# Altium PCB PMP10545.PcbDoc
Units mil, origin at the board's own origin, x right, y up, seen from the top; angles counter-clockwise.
Board outline 3000 x 2500 mil, 2 copper layers (Top Layer, Bottom Layer), stack 62 mil thick; 63 components, 23 nets, 122 pads, 5 vias.
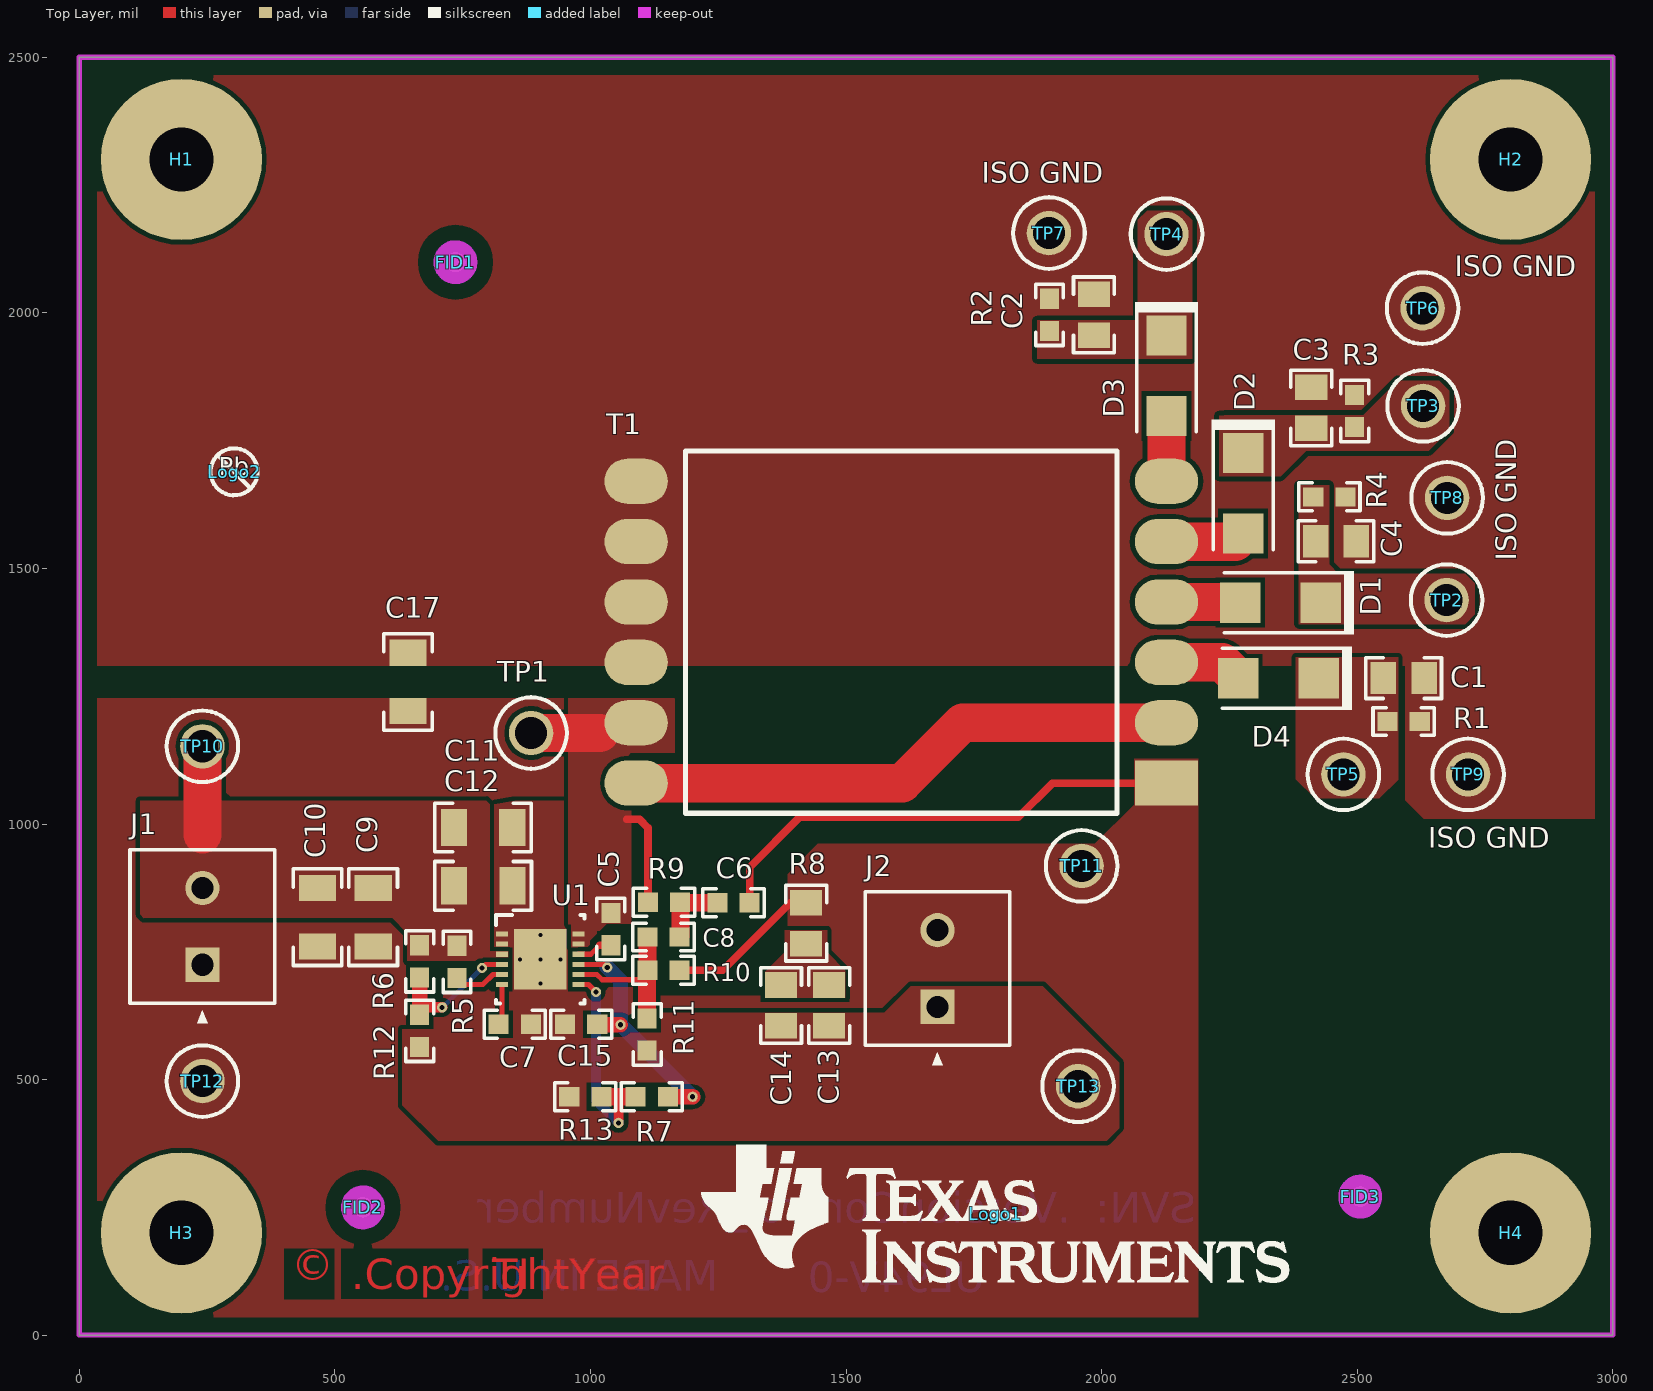
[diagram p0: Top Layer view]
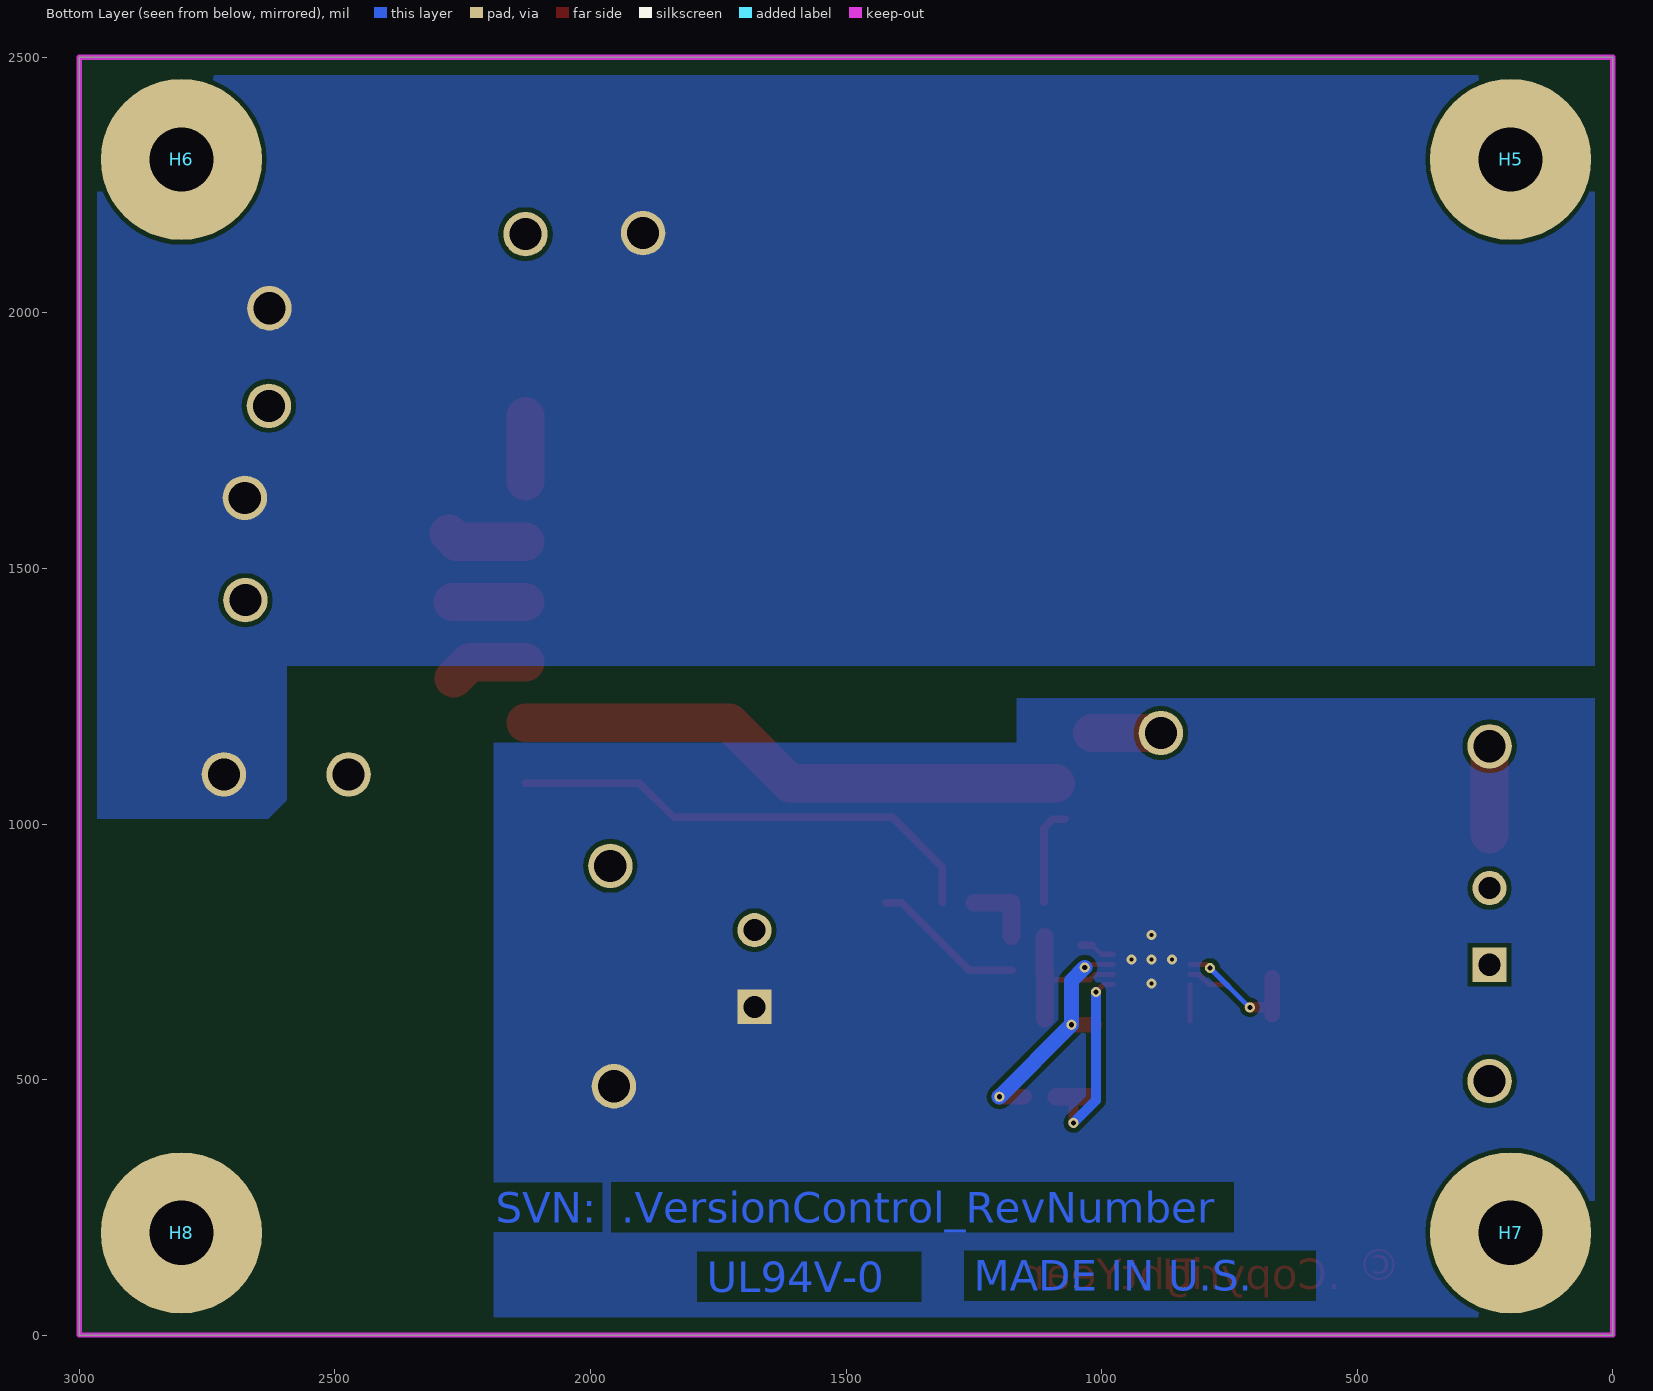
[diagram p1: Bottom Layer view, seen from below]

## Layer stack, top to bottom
Top Solder: solder mask 0.4, Solder Resist, Dk 3.5
Top Layer: signal copper 1.4
Dielectric1: core 59.2, FR-4, Dk 4.8
Bottom Layer: signal copper 1.4
Bottom Solder: solder mask 0.4, Solder Resist, Dk 3.5

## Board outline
0,0 3000,0 3000,2500 0,2500

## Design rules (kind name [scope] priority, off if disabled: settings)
AcuteAngle [All] p1: minimum=4.50000000000000E+0001 checktracksonly=FALSE
AssemblyTestPointUsage [All] p1: valid=2
Clearance Clearance_BoardEdge_MountingHoles [OnCopper and InComponentClass('Mounting Holes') vs IsKeepOut] p1: gap=30
Clearance Clearance_BoardEdge_Poly [OnCopper and InPoly vs IsKeepOut] p2: gap=30
Clearance Clearance_BoardEdge [OnCopper and Not InComponentClass('Logo') and not InComponentClass('FiducialMark') and not InRegion(1000,500,4000,800) and Not IsKeepout vs IsKeepOut] p3: gap=30
Clearance Clearance_Poly [InPolygon] p4: gap=9
Clearance [All] p5: gap=9
ComponentClearance ComponentClearance_Shunt [InComponentClass('Header') vs InComponentClass('Shunt')] p1: gap=0 collisioncheckmode=3 verticalgap=0 showdistances=FALSE
ComponentClearance ComponentClearance_MountingHoles_FiducialMarks [InComponentClass('Mounting Holes') vs InComponentClass('FiducialMark')] p2: gap=50 collisioncheckmode=3 verticalgap=10 showdistances=FALSE
ComponentClearance ComponentClearance_Logo [InComponentClass('Logo')] p3: gap=50 collisioncheckmode=3 verticalgap=10 showdistances=FALSE
ComponentClearance ComponentClearance_ScrewToNut [(HasFootprint('NY PMS 440 0025 PH')) vs (HasFootprint('Keystone_1902C'))] p4: gap=5 collisioncheckmode=3 verticalgap=10 showdistances=FALSE
ComponentClearance ComponentClearance_MountingHoles [InComponentClass('Mounting Holes')] p5: gap=50 collisioncheckmode=3 verticalgap=100000 showdistances=FALSE
ComponentClearance ComponentClearance_SmallPassives [HasFootprint('0201*') or HasFootprint('0402*') or HasFootprint('0508') or HasFootprint('0603*') or HasFootprint('0612') or HasFootprint('0805*') or HasFootprint('0815*') or HasFootprint('0830*') or HasFootprint('1206*') or HasFootprint('1210*') or HasFootprint('1808*') or HasFootprint('1812*') or HasFootprint('1825*') or HasFootprint('2010*') or HasFootprint('2220*') or HasFootprint('2225*') or HasFootprint('2512*') or HasFootprint('2728*') or HasFootprint('3518*') vs HasFootprint('0201*') or HasFootprint('0402*') or HasFootprint('0508') or HasFootprint('0603*') or HasFootprint('0612') or HasFootprint('0805*') or HasFootprint('0815*') or HasFootprint('0830*') or HasFootprint('1206*') or HasFootprint('1210*') or HasFootprint('1808*') or HasFootprint('1812*') or HasFootprint('1825*') or HasFootprint('2010*') or HasFootprint('2220*') or HasFootprint('2225*') or HasFootprint('2512*') or HasFootprint('2728*') or HasFootprint('3518*')] p6: gap=20 collisioncheckmode=3 verticalgap=10 showdistances=FALSE
ComponentClearance ComponentClearance_THtoSMT [IsThruComponent vs IsSMTComponent] p7: gap=35 collisioncheckmode=3 verticalgap=30 showdistances=FALSE
ComponentClearance ComponentClearance_THtoTH [IsThruComponent vs IsThruComponent] p8: gap=50 collisioncheckmode=3 verticalgap=30 showdistances=FALSE
ComponentClearance [All] p9: gap=20 collisioncheckmode=3 verticalgap=10 showdistances=FALSE
DiffPairsRouting [All] p1: maxlimit=100 minlimit=10 mostfreqgap=10 toplayer_minwidth=15 toplayer_maxwidth=15 toplayer_prefwidth=15 bottomlayer_minwidth=15 bottomlayer_maxwidth=15 bottomlayer_prefwidth=15 maxuncoupledlength=1000
FabricationTestPointUsage TestPointUsage [All] p1: valid=2 allowmultiple=FALSE
FabricationTestpoint Testpoint [All] p1: side=3 testpointundercomponent=TRUE minsize=40 maxsize=100 preferedsize=60 minholesize=0 maxholesize=40 preferedholesize=32 testpointgrid=1 allowsidetop=TRUE allowsidebottom=TRUE usegrid=TRUE gridtolerance=0.01
FanoutControl Fanout_LCC [IsLCC] p1: bgadir=Out bgaviamode=Centered fanoutstyle=Auto fanoutdirection=Alternating viagrid=1 // Fanout_LCC (Default Rule)
FanoutControl Fanout_BGA [IsBGA] p2: bgadir=Out bgaviamode=Centered fanoutstyle=Auto fanoutdirection=Alternating viagrid=1 // Fanout_BGA (Default Rule)
FanoutControl Fanout_Default [All] p4: bgadir=Out bgaviamode=Centered fanoutstyle=Auto fanoutdirection=Alternating viagrid=1 // Fanout_Default (Default Rule)
FanoutControl Fanout_Small [(CompPinCount < 5)] p5: bgadir=Out bgaviamode=Centered fanoutstyle=Auto fanoutdirection=OutThenIn viagrid=1 // Fanout_Small (Default Rule)
HoleSize [All] p1: absolutevalues=TRUE maxlimit=251 minlimit=8 maxpercent=80.000 minpercent=20.000
MinimumAnnularRing MinimumAnnularRing_ThermalPadVias [IsVia and InAnyComponent] p1: minimumring=5
MinimumAnnularRing [All] p2: minimumring=5
MinimumSolderMaskSliver MinimumSolderMaskSliver_Logo [InComponentClass('Logo') vs InComponentClass('Logo')] p1: minsoldermaskwidth=0.7
MinimumSolderMaskSliver [All] p2: minsoldermaskwidth=3.94
PlaneConnect [All] p1: planeconnectstyle=Direct reliefexpansion=10 reliefentries=4 reliefconductorwidth=10 reliefairgap=10
PolygonConnect [All] p1: connectstyle=Direct reliefconductorwidth=10 reliefentries=4 polygonreliefangle="90 Angle" airgapwidth=10
RoutingVias ThermalPadVias [IsVia and InAnyComponent] p1: holewidth=7.87 width=19.68 viastyle="Through Hole" minholewidth=10 minwidth=20 maxholewidth=12.99 maxwidth=23.62
RoutingVias [All] p2: holewidth=16 width=34 viastyle="Through Hole" minholewidth=10 minwidth=20 maxholewidth=40 maxwidth=65
SMDToCorner [All] p1: distance=30000
SilkToSilkClearance SilkToSilkClearance_Pb-FreeLogo [(HasFootprint('Pb-Free_Overlay_Medium') OR HasFootprint('Pb-Free_Overlay_Small')) vs (HasFootprint('Pb-Free_Overlay_Medium') OR HasFootprint('Pb-Free_Overlay_Small'))] p1: silktosilkclearance=0
SilkToSilkClearance [All] p2: silktosilkclearance=5
SilkToSolderMaskClearance SilkscreenOverComponentPads [IsPad] p1: minsilkscreentomaskgap=5 clearancetoexposedcopper=TRUE
SolderMaskExpansion [All] p1: expansion=1.97
UnpouredPolygon [All] p1: allowunpoured=FALSE
Width [All] p1: maxlimit=100 minlimit=6 preferedwidth=10 checkconnectedcopper=TRUE
15 further rules are at their usual default settings.

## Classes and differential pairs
component class "Mounting Holes": H1 H2 H3 H4
component class Logo: Logo1
component class PMP10545_Hardware_ANSI-B: FID1 FID2 FID3 H1 H2 H3 H4 H5 H6 H7 H8 Logo1 Logo2
component class FiducialMark: FID1 FID2 FID3
component class "PMP10545 Schematic rev 4SchDoc": C1 C2 C3 C4 C5 C6 C7 C8 C9 C10 C11 C12 C13 C14 C15 C17 D1 D2 D3 D4 J1 J2 R1 R2 R3 R4 R5 R6 R7 R8 R9 R10 R11 R12 R13 T1 TP1 TP2 TP3 TP4 TP5 TP6 TP7 TP8 TP9 TP10 TP11 TP12 TP13 U1

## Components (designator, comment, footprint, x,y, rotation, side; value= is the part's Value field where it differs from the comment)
C1 "EMK212BJ106KG-T" 0805_HV 2591,1285.52 r0 top
C2 "EMK212BJ106KG-T" 0805_HV 1985,1996 r90 top
C3 "EMK212BJ106KG-T" 0805_HV 2410,1814 r90 top
C4 "EMK212BJ106KG-T" 0805_HV 2458.55,1553 r0 top
C5 "C0603C104J3RAC" 0603 1039.99,794.35 r270 top
C6 "C0603C222K5RAC" 0603 1280,846 r0 top
C7 "GRM188R71C223KA01D" 0603 851.99,608.35 r0 top
C8 "C0603C104J3RAC" 0603 1143,779 r180 top
C9 "GRM31CR61H225KA88L" 1206 574.99,817.67 r270 top
C10 "GRM31CR61H225KA88L" 1206 465.99,817.67 r270 top
C11 "GRM31CR61H225KA88L" 1206 789.99,993.04 r0 top
C12 "GRM31CR61H225KA88L" 1206 790.3,879.04 r0 top
C13 "EMK212BJ106KG-T" 0805_HV 1466.99,645.04 r270 top
C14 "EMK212BJ106KG-T" 0805_HV 1372.99,645.04 r270 top
C15 "GRM188R71E105KA12D" 0603 981.99,608.35 r180 top
C17 "VJ1206A102JXGAT5Z" 1206 643,1278 r270 top
D1 "ES1A-13-F" SMA 2350,1433 r180 top
D2 "ES1A-13-F" SMA 2277,1647 r270 top
D3 "ES1A-13-F" SMA 2127,1877 r270 top
D4 "ES1A-13-F" SMA 2346,1285 r180 top
FID1 "Fiducial" Fiducial10-20 736,2099 r0 top
FID2 "Fiducial" Fiducial10-20 555,250 r0 top
FID3 "Fiducial" Fiducial10-20 2506,271 r0 top
H1 "NY PMS 440 0025 PH" "NY PMS 440 0025 PH" 200,2300 r0 top locked
H2 "NY PMS 440 0025 PH" "NY PMS 440 0025 PH" 2800,2300 r0 top locked
H3 "NY PMS 440 0025 PH" "NY PMS 440 0025 PH" 200,200 r0 top locked
H4 "NY PMS 440 0025 PH" "NY PMS 440 0025 PH" 2800,200 r0 top locked
H5 "1902C" Keystone_1902C 200,2300 r180 bottom locked
H6 "1902C" Keystone_1902C 2800,2300 r180 bottom locked
H7 "1902C" Keystone_1902C 200,200 r180 bottom locked
H8 "1902C" Keystone_1902C 2800,200 r180 bottom locked
J1 "Vin" PhoenixConact_1727010 240.99,799.67 r90 top
J2 "Vout Primary" PhoenixConact_1727010 1678.99,717.35 r90 top
Logo1 "Texas Instruments" TI_Stacked_Overlay_Medium 1792,238 r0 top
Logo2 "Pb-Free Symbol" Pb-Free_Overlay_Small 303,1689 r0 top
R1 "CRCW06032K00FKEA" 0603 2591,1200.52 r180 top
R2 "CRCW06032K00FKEA" 0603 1898,1996 r270 top
R3 "CRCW06032K00FKEA" 0603 2495,1808 r270 top
R4 "CRCW06032K00FKEA" 0603 2445.55,1640 r180 top
R5 "CRCW0603487KFKEA" 0603 738.99,730.35 r90 top
R6 "RC0603FR-07127KL" 0603 665.99,731.35 r90 top
R7 "CRCW06030000Z0EA" 0603 1119.99,466.35 r180 top
R8 "ERJ-6RQFR47V" 0805_HV 1422,806 r90 top
R9 "CRCW0603100KFKEA" 0603 1144,847 r0 top
R10 "CRCW060310K0FKEA" 0603 1143,714 r0 top
R11 "CRCW06032K00FKEA" 0603 1110.99,588.35 r90 top
R12 "CRCW060318K2FKEA" 0603 665.99,595.35 r90 top
R13 "CRCW06030000Z0EA" 0603 989.99,466.35 r0 top
T1 "Coiltronics, VP5-0083" VP5 2127,1080 r180 top
TP1 "Vsw Pri" Keystone5014 884,1178 r0 top
TP2 "Vo1" Keystone5014 2675,1438 r0 top
TP3 "Vo2" Keystone5014 2629,1818 r0 top
TP4 "Vo3" Keystone5014 2127,2154 r0 top
TP5 "Vo4" Keystone5014 2473,1097 r0 top
TP6 "ISO GND" Keystone5011 2628,2009 r0 top
TP7 "ISO GND" Keystone5011 1897,2156 r0 top
TP8 "ISO GND" Keystone5011 2676,1638 r0 top
TP9 "ISO GND" Keystone5011 2717,1097 r0 top
TP10 "+Vin" Keystone5010 241,1152 r0 top
TP11 "GNDout" Keystone5011 1961,918 r0 top
TP12 "GNDin" Keystone5011 241,497 r0 top
TP13 "-Vout" Keystone5127 1954,487 r0 top
U1 "LM5160DNT" DNT0012B 901.99,735.35 r0 top

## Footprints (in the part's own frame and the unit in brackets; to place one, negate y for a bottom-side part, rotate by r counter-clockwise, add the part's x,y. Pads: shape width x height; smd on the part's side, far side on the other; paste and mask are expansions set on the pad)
0603 [mm] "0603 from SM-752 data"
  rect 1x0.95 smd: 1(-0.8,0) 2(0.8,0)
  silkscreen extent -1.52,-0.69 1.52,0.69, body extent -0.87,-0.47 0.87,0.47, height 0.85
0805_HV [mil] "0805 with 30mil clearance between pads"
  rect 50x63 smd: 1(-40,0) 2(40,0)
  silkscreen extent -74,-40 74,40, body extent -43,-29 43,29, height 43
1206 [mm] "1206 from SM-752 data"
  rect 1.3x1.85 smd: 1(-1.45,0) 2(1.45,0)
  silkscreen extent -2.4,-1.21 2.4,1.21, body extent -1.7,-0.9 1.7,0.9, height 1.35
DNT0012B [mm] "SON, 12-Leads, Body 4x4mm, Pitch 0.5mm"
  rect 0.6x0.25 smd: 1(-1.9,1.25) 2(-1.9,0.75) 3(-1.9,0.25) 4(-1.9,-0.25) 5(-1.9,-0.75) 6(-1.9,-1.25) 7(1.9,-1.25) 8(1.9,-0.75) 9(1.9,-0.25) 10(1.9,0.25) 11(1.9,0.75) 12(1.9,1.25)
  rect 2.6x3 smd paste-1.3: 13(0,0)
  silkscreen extent -2.2,-2.2 2.2,2.2, body extent -2.05,-2.05 2.05,2.05, height 0.81
Fiducial10-20 [mm]
  round 1 smd mask+0.5: 1(0,0)
  Top Layer keep-out circle w1.178: c0,0 r0.5
Keystone5010 [mil] "Keystone Multipurpose loops"
  round 87 hole 63: 1(0,0)
  silkscreen extent -70,-70 70,70, body extent -63,-63 63,62, height 319
Keystone5011 [mil] "Keystone Multipurpose loops"
  round 87 hole 63: 1(0,0)
  silkscreen extent -70,-70 70,70, body extent -63,-63 63,62, height 319
Keystone5014 [mil] "Keystone Multipurpose loops"
  round 87 hole 63: 1(0,0)
  silkscreen extent -70,-70 70,70, body extent -63,-63 63,62, height 319
Keystone5127 [mil] "Keystone Multipurpose loops"
  round 87 hole 63: 1(0,0)
  silkscreen extent -70,-70 70,70, body extent -63,-63 63,62, height 319
Keystone_1902C [mil] "Hex Standoff, 4-40 threaded, nylon"
  body extent -145,-126 146,126, height 501
"NY PMS 440 0025 PH" [mm] "4-40 nylon screw and mounting hole"
  round 8 hole 3.2: 1(0,0)
  body extent -3.3,-3.3 3.3,3.3, height 2.69
Pb-Free_Overlay_Small [mil]
  silkscreen extent -46,-46 46,46
PhoenixConact_1727010 [mm]
  rect 1.7x1.7 hole 1.1: 1(-1.905,0)
  round 1.7 hole 1.1: 2(1.905,0)
  silkscreen extent -4.8,-3.6 3.81,3.6, body extent -3.81,-3.6 3.81,3.7, height 8.52
SMA [mm] "Molded Diode, 2-Leads, Body 4.3x2.6mm, IPC Medium Density, based on OnSemi component dimensions and land pattern"
  rect 2x2 smd: 1(-2,0) 2(2,0)
  silkscreen extent -3.66,-1.57 2.79,1.57, body extent -2.6,-1.3 2.6,1.3, height 2.42
TI_Stacked_Overlay_Medium [mil]
  silkscreen extent -576,-136 576,134
VP5 [mm]
  rect 3.15x2.25 smd: 1(0,0)
  oval 3.15x2.25 smd: 2(0,-3) 3(0,-6) 4(0,-9) 5(0,-12) 6(0,-15) 7(26.35,-15) 8(26.35,-12) 9(26.35,-9) 10(26.35,-6) 11(26.35,-3) 12(26.35,0)
  silkscreen extent 2.46,-16.5 23.89,1.5

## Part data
C1 C2 C3 C4 C13 C14: "CAP, CERM, 10uF, 16V, +/-10%, X5R, 0805"
C5 C8: "CAP, CERM, 0.1uF, 25V, +/-5%, X7R, 0603"
C6: "CAP, CERM, 2200pF, 50V, +/-10%, X7R, 0603"
C7: "CAP, CERM, 0.022uF, 16V, +/-10%, X7R, 0603"
C9 C10 C11 C12: "CAP, CERM, 2.2uF, 50V, +/-10%, X5R, 1206"
C15: "CAP, CERM, 1uF, 25V, +/-10%, X7R, 0603"
C17: "CAP, CERM, 1000pF, 1000V, +/-5%, C0G/NP0, 1206"
D1 D2 D3 D4: "Diode, Ultrafast, 50V, 1A, SMA"
FID1 FID2 FID3: "Fiducial mark.  There is nothing to buy or mount."
H1 H2 H3 H4: "Machine Screw, Round, #4-40 x 1/4, Nylon, Philips panhead"
H5 H6 H7 H8: "Standoff, Hex, 0.5\"L #4-40 Nylon"
J1 J2: library part 1727010, "Conn Term Block, 2POS, 3.81mm, TH"
Logo1: library part TI_Logo, "Texas Instrument Corporate Signature"
Logo2: library part Pb-Free
R1 R2 R3 R4 R11: "RES, 2.00k ohm, 1%, 0.1W, 0603"
R5: "RES, 487k ohm, 1%, 0.1W, 0603"
R6: "RES, 127k ohm, 1%, 0.1W, 0603"
R7 R13: "RES, 0, 5%, 0.1 W, 0603"
R8: "RES, 0.47 ohm, 1%, 0.125W, 0805"
R9: "RES, 100k ohm, 1%, 0.1W, 0603"
R10: "RES, 10.0k ohm, 1%, 0.1W, 0603"
R12: "RES, 18.2k ohm, 1%, 0.1W, 0603"
T1: library part VP5XFMR
TP1 TP2 TP3 TP4 TP5: library part 5014, "Test Point, Multipurpose, Yellow, TH"
TP6 TP7 TP8 TP9 TP11 TP12: library part 5011, "Test Point, Multipurpose, Black, TH"
TP10: library part 5010, "Test Point, Multipurpose, Red, TH"
TP13: library part 5127, "Test Point, Multipurpose, Blue, TH"
U1: "Wide Input 65V, 1.5A Synchronous Step-Down DC-DC Converter, DNT0012B"

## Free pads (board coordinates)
  round 20 hole 10: 0(709.99,641.35) 0(787.99,718.35) 0(1010.99,671.35) 0(1032.99,719.35) 0(1054.99,415.35) 0(1058.99,607.35) 0(1199.99,466.35)

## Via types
v1: diameter 19.68, hole 7.87, Top Layer to Bottom Layer, 5 vias

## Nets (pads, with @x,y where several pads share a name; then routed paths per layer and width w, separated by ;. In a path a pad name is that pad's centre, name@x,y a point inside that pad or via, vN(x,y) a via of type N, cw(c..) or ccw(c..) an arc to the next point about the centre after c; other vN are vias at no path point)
-VOUT: C7.2 C11.2 C12.2 C13.2 C14.2 C15.2 J2.1 R11.1 R12.1 R13.1 TP13.1 U1.1 U1.2 U1.13
  other v1: 901.99,688.11 862.62,735.35 901.99,735.35 941.36,735.35 901.99,782.6
BST: C5.2 U1.10 | length 70.5
  Top Layer w10: U1.10 1000.83,745.2 1018.49,762.86
  Top Layer w15: 1018.49,762.86 C5.2
"CO PRI": C13.1 C14.1 R8.1
EN: pad.0@709.99,641.35 pad.0@787.99,718.35 R6.1 R12.2 U1.4 | length 253.6
  Top Layer w10: pad.0@787.99,718.35 795.14,725.51 U1.4
  Top Layer w20: R12.2@680.49,641.35 pad.0@709.99,641.35
  Top Layer w30: R12.2 R6.1
  Bottom Layer w10: pad.0@710.99,641.35 pad.0@787.99,718.35
FB: C8.2 R10.1 R11.2 U1.8 | length 292.7
  Top Layer w10: U1.8 1012.57,705.83 1023.05,695.35 R10.1@1106.49,695.35
  Top Layer w35: R11.2 R10.1@1110.99,714 ; R10.1@1111.5,714.52 C8.2
FPWM: pad.0@1010.99,671.35 pad.0@1054.99,415.35 R7.2 R13.2 U1.7 | length 432.6
  Top Layer w10: U1.7 996.2,686.14 pad.0@1010.99,671.35
  Top Layer w20: pad.0@1054.99,415.35 1054.99,466.35
  Top Layer w35: R13.2 1054.99,466.35 R7.2
  Bottom Layer w20: pad.0@1010.99,671.35 1010.99,459.35 pad.0@1054.99,415.35
GND: C6.2 C9.2 C10.2 C17.2 J1.1 J2.2 R8.2 R10.2 T1.1 TP11.1 TP12.1 | length 1255.3
  Top Layer w15: R10.2 1259,714 1391,846 R8.2 ; C6.2 1311.5,915.5 1409,1013 1837,1013 1904,1080 T1.1
"GND ISO": C1.2 C2.2 C3.2 C4.2 C17.1 R1.1 R2.1 R3.1 R4.1 T1.7 T1.8 T1.9 T1.10 TP6.1 TP7.1 TP8.1 TP9.1
NetT1_2: T1.2 T1.12 | length 1086.3
  Top Layer w75: T1.12 1610,1080 1728.11,1198.11 T1.2
RON: R5.1 U1.5 | length 81.8
  Top Layer w10: R5.1@753.49,686.35 789.99,686.35 809.46,705.83 U1.5
SS: C7.1 U1.6 | length 71.1
  Top Layer w10: C7.1@827.18,615.05 U1.6
VCC: C15.1 pad.0@1032.99,719.35 pad.0@1058.99,607.35 pad.0@1199.99,466.35 R7.1 U1.9 | length 473.9
  Top Layer w10: U1.9 1026.83,725.51 pad.0@1032.99,719.35
  Top Layer w30: C15.1@1014.48,607.35 pad.0@1058.99,607.35 ; R7.1 pad.0@1199.99,466.35
  Bottom Layer w30: pad.0@1032.99,719.35 1058.99,693.35 1058.99,607.35 pad.0@1199.99,466.35
VIN: C9.1 C10.1 C11.1 C12.1 J1.2 R5.2 R6.2 TP10.1 U1.3 | length 172
  Top Layer w75: 241,980 TP10.1
"VO SEC1": C4.1 D1.1 R4.2 TP2.1
"VO SEC2": C3.1 D2.1 R3.2 TP3.1
"VO SEC3": C2.1 D3.1 R2.2 TP4.1
"VO SEC4": C1.1 D4.1 R1.2 TP5.1
VRIPL: C6.1 C8.1 R9.2 | length 137
  Top Layer w35: C8.1@1176.5,781 1176.5,846 C6.1
"VSW PRI": C5.1 R9.1 T1.11 TP1.1 U1.11 U1.12 | length 327.8
  Top Layer w15: 1071,1009 1096,1009 1112.5,992.5 R9.1
  Top Layer w75: TP1.1 1018,1178
"VSW SEC1": D1.2 T1.4 | length 142.9
  Top Layer w75: T1.4 D1.2@2269.93,1434.33
"VSW SEC2": D2.2 T1.5 | length 156.6
  Top Layer w75: T1.5 2261.18,1552.44 D2.2
"VSW SEC3": D3.2 T1.6 | length 127.7
  Top Layer w75: T1.6 D3.2
"VSW SEC4": D4.2 T1.3 | length 153.2
  Top Layer w75: T1.3 2236.04,1316.22 D4.2
pads on no net: FID1.1 FID2.1 FID3.1 H1.1 H2.1 H3.1 H4.1

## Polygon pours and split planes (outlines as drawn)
GND on Top Layer "Top Layer-GND" (solid, remove dead copper, pour order 10): 0,1246 1125,1246 1125,664 1386,664 1386,902 1445,961 1987,961 2064,1038 2064,1128 2189,1128 2189,0 0,0
"CO PRI" on Top Layer "Top Layer-Co Pri" (solid, remove dead copper, pour order 6): 1342,711 1380,749 1380,792 1463,792 1463,749 1499,713 1499,660 1342,660
"VSW PRI" on Top Layer "Top Layer-Vsw Pri" (solid, remove dead copper, pour order 4): 956,759 956,753 957,754 999,754 999,772.07 1021.29,794.35 1031.93,805 1080,805 1080,1138 1079,1139 1165,1139 1165,1245 1164,1246 1155,1246 957,1246 957,1238 957,754
VIN on Top Layer "Top Layer-Vin" (solid, remove dead copper, pour order 2): 838.99,751.35 838.99,732.35 641.99,732.35 641.99,786.35 611.99,816.35 119,816 119,1045 802.99,1045.35 802.99,751.35
"VO SEC3" on Top Layer "Top Layer-Vo3" (solid, remove dead copper, pour order 12): 1874,1974 1874,1985 1885,1985 2053,1985 2071,1985 2071,2024 2071,2182 2089,2200 2105,2200 2158,2200 2177,2181 2177,2168 2177,1910 2165,1910 1874,1910 1874,1919 1874,1974
"VO SEC1" on Top Layer "Top Layer-Vo1" (solid, remove dead copper, pour order 16): 2386,1397 2386,1391 2396,1391 2711,1391 2730,1410 2730,1430 2730,1471 2711,1490 2698,1490 2463,1490 2445,1508 2445,1526 2445,1663 2425,1663 2386,1663 2386,1648 2386,1397
"VO SEC4" on Top Layer "Top Layer-Vo4" (solid, remove dead copper, pour order 18): 2380,1326 2390,1326 2580,1326 2580,1308 2580,1087 2543,1050 2496,1050 2418,1050 2380,1088 2380,1100
"VO SEC2" on Top Layer "Top Layer-Vo2" (solid, remove dead copper, pour order 14): 2661,1867 2680,1848 2680,1770 2640,1730 2400,1730 2350,1680 2230,1680 2230,1799 2239,1799 2240,1800 2512,1800 2580,1868 2581,1867
"GND ISO" on Top Layer "Top Layer-ISO GND" (solid, remove dead copper, pour order 20): 0,1310 23,1310 133,1310 2594,1310 2594,1286 2594,1046 2630,1010 2653,1010 3000,1010 3000,1022 3000,2500 0,2500 0,1310
-VOUT on Top Layer "Top Layer--Vout" (solid, remove dead copper, pour order 8): 632,1041 632,1045 654,1045 1083,1045 1083,1017 1083,631 1095,631 1575,631 1624,680 1627,683 1722,683 1885,683 2035,533 2035,514 2035,405 2010,380 1972,380 702,380 632,450 632,462
-VOUT on Bottom Layer "Bottom Layer--Vout" (solid, remove dead copper, pour order 22): 0,1246 16,1246 1166,1246 1166,1199 1166,1159 1174,1159 2189,1159 2189,1150 2189,0 2165,0 0,0
"GND ISO" on Bottom Layer "Bottom Layer-ISO GND" (solid, remove dead copper, pour order 24): 0,1310 15,1310 2594,1310 2594,1299 2594,1046 2630,1010 3000,1010 3000,1020 3000,2500 0,2500

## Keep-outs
Keep-Out Layer:
  the board outline again, w10
  text ".Layer_Name" at 577,-858.49 h60

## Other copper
Top Layer:
  text ".CopyrightYear" at 532,90 h60
  text "TI" at 808,90 h60
  text "©" at 415,86.48 h105
  text ".Layer_Name" at 577,-858.49 h60
Bottom Layer:
  text ".VersionControl_RevNumber" at 1940,220 h60
  text "SVN:" at 2185,220 h60
  text "MADE IN U.S." at 1250,86.5 h60
  text "UL94V-0" at 1772,84 h60
  text ".Layer_Name" at 577,-858.49 h60

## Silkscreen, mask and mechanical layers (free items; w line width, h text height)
Top Overlay:
  drawing of 191 lines, arcs and shapes, not listed
  text "Layer" at 5812,3546 h60
  text "Name" at 6221.91,3546 h60
  text "Material" at 7151.66,3546 h60
  text "Thickness" at 8011.42,3546 h60
  text "Constant" at 8661.26,3546 h60
  text "Board Layer Stack" at 9231.12,3546 h60
  text "1" at 5812,3426 h60
  text "Top Overlay" at 6221.91,3426 h60
  text "2" at 5812,3306 h60
  text "Top Solder" at 6221.91,3306 h60
  text "Solder Resist" at 7151.66,3306 h60
  text "0.40mil" at 8011.42,3306 h60
  text "3.5" at 8661.26,3306 h60
  text "3" at 5812,3186 h60
  text "Top Layer" at 6221.91,3186 h60
  text "Copper" at 7151.66,3186 h60
  text "1.40mil" at 8011.42,3186 h60
  text "4" at 5812,3066 h60
  text "Dielectric1" at 6221.91,3066 h60
  text "FR-4" at 7151.66,3066 h60
  text "59.20mil" at 8011.42,3066 h60
  text "4.8" at 8661.26,3066 h60
  text "5" at 5812,2946 h60
  text "Bottom Layer" at 6221.91,2946 h60
  text "Copper" at 7151.66,2946 h60
  text "1.40mil" at 8011.42,2946 h60
  text "6" at 5812,2826 h60
  text "Bottom Solder" at 6221.91,2826 h60
  text "Solder Resist" at 7151.66,2826 h60
  text "0.40mil" at 8011.42,2826 h60
  text "3.5" at 8661.26,2826 h60
  text "7" at 5812,2706 h60
  text "Bottom Overlay" at 6221.91,2706 h60
  text ".Layer_Name" at 577,-858.49 h60
Bottom Overlay:
  text ".Layer_Name" at 577,-858.49 h60
Top Paste:
  text ".Layer_Name" at 577,-858.49 h60
Bottom Paste:
  text ".Layer_Name" at 577,-858.49 h60
Top Solder:
  text ".Layer_Name" at 577,-858.49 h60
  text ".Layer_Name" at 577,-858.49 h60
Bottom Solder:
  text ".Layer_Name" at 577,-858.49 h60
Drill Guide:
  text ".Layer_Name" at 577,-858.49 h60
M1 Board Outline:
  the board outline again, w10
  text ".Layer_Name" at 577,-858.49 h60
M2 Board Dimensions:
  rectangle: 0,-285.5 125,-160.5
  rectangle: 125,-410.5 500,-285.5
  lines w7: 0,-285.5 1000,-285.5 ; 125,-410.5 125,-160.5 ; 250,-410.5 250,-160.5 ; 500,-410.5 500,-160.5 ; 750,-410.5 750,-160.5 ; 0,-410.5 1000,-410.5 1000,-160.5 0,-160.5 0,-410.5
  text ".Layer_Name" at 577,-858.49 h60
M3 3D STEP Top:
  text ".Layer_Name" at 577,-858.49 h60
M4 3D STEP Bottom:
  text ".Layer_Name" at 577,-858.49 h60
M5 Assembly Top:
  lines w10: -292,-930.17 6308,-930.17 ; -292,-726.83 6310,-726.83 ; -292,-523.5 -292,-1133.5 3713,-1133.5 6310,-1133.5 6310,-523.5 -291.5,-523.5 -291.5,-1133.5 1284,-1133.5 ; 2173,-1133.5 2173,-523.5 ; 3440,-726.83 3440,-523.5 ; 4280,-726.83 4280,-523.5 ; 4902,-1140 4902,-937.17
  text "COMPONENTS MARKED 'DNP' SHOULD NOT BE POPULATED." at 1153.5,-318.5 h60
  text "ASSEMBLY VARIANT:" at 1153,-434 h60
  text ".VariantName" at 2189,-434 h60
  text "PCB VIEWED FROM TOP SIDE" at -228.5,-655.67 h60
  text "BOARD #:" at 2248,-655.67 h60
  text ".PRJ_Number" at 2793.5,-655.67 h60
  text "REV:" at 3638,-655.67 h60
  text ".PCB_Rev" at 3929.5,-655.67 h60
  text "SVN REV:" at 4476,-655.67 h60
  text ".VersionControl_RevNumber" at 4982,-655.67 h60
  text "IGNORE ->" at -228.5,-858.49 h60
  text "PLOT NAME =" at -228.5,-1064.34 h60
  text ".plot_File_Name" at 577,-1064.34 h60
  text "GENERATED    :" at 2250,-1064.34 h60
  text ".Print_Date" at 3119.5,-1064.34 h60
  text ".Print_Time" at 3848.5,-1064.34 h60
  text "TEXAS INSTRUMENTS" at 5113,-1064.34 h60
M6 Assembly Bottom:
  lines w10: -292.5,-727.33 6309.5,-727.33 ; -290.5,-930.67 6309.5,-930.67 ; 1115.5,-1140.5 1115.5,-937.67 ; 1737.5,-727.33 1737.5,-524 ; 2577.5,-727.33 2577.5,-524 ; 3844.5,-1134 3844.5,-524 ; 4733.5,-1134 6309,-1134 6309,-524 -292.5,-524 -292.5,-1134 2304.5,-1134 6309.5,-1134 6309.5,-524
  text "COMPONENTS MARKED 'DNP' SHOULD NOT BE POPULATED." at 6102,-318 h60
  text ".VariantName" at 5058,-434 h60
  text "ASSEMBLY VARIANT:" at 6097,-434 h60
  text ".VersionControl_RevNumber" at 1035.5,-656.17 h60
  text "SVN REV:" at 1541.5,-656.17 h60
  text ".PCB_Rev" at 2088,-656.17 h60
  text "REV:" at 2379.5,-656.17 h60
  text ".PRJ_Number" at 3224,-656.17 h60
  text "BOARD #:" at 3769.5,-656.17 h60
  text "PCB VIEWED FROM BOTTOM SIDE" at 6246,-656.17 h60
  text "IGNORE ->" at 2547.85,-858.49 h60
  text "TEXAS INSTRUMENTS" at 904.5,-1064.84 h60
  text ".Print_Time" at 2169,-1064.84 h60
  text ".Print_Date" at 2898,-1064.84 h60
  text "GENERATED    :" at 3767.5,-1064.84 h60
  text ".plot_File_Name" at 5440.5,-1064.84 h60
  text "PLOT NAME =" at 6246,-1064.84 h60
M7 LPKF Text Top:
  text "PMP10545" at 629,2271 h100
M9 Title Sheet:
  drawing of 57 lines, arcs and shapes, not listed
  text "1" at 739.84,8036.5 h70
  text "2" at 3235.5,8036.5 h70
  text "3" at 5724.84,8036.5 h70
  text "4" at 8231.51,8036.5 h70
  text "5" at 10730.5,8036.5 h70
  text "6" at 13235.5,8036.5 h70
  text "A" at -416.5,6893.5 h70
  text "A" at 14383.5,6893.5 h70
  text "B" at -416.5,4513.5 h70
  text "B" at 14383.5,4513.5 h70
  text "C" at -416.5,2138.5 h70
  text "C" at 14383.5,2138.5 h70
  text "PROJECT TITLE:" at 11343.5,277.5 h45
  text ".PRJ_Title" at 11393.5,144.17 h70
  text "DESIGNED FOR:" at 11343.5,-23.5 h45
  text ".PRJ_Customer" at 11393.5,-163.5 h70
  text "D" at -416.5,-231.5 h70
  text "D" at 14383.5,-231.5 h70
  text "FILE NAME:" at 11343.5,-323.5 h45
  text ".PCB_File_Name_No_Path" at 11393.5,-443.5 h70
  text "Texas Instruments (TI) and/or its licensors do not warrant the accuracy or completeness of this specification" at 6374,-605.34 h45
  text "ENGINEER:" at 11343.5,-613.5 h45
  text "LAYOUT BY:" at 12848.5,-613.5 h45
  text "or any information contained therein. TI and/or its licensors do not warrant that this design will meet" at 6329.01,-718 h45
  text ".PRJ_Engineer" at 11393.5,-768.49 h70
  text ".PCB_Layout" at 12899,-768.49 h70
  text "the specifications, will be suitable for your application or fit for any particular purpose, or will operate in" at 6329.01,-830.67 h45
  text ".Layer_Name" at 577,-858.49 h60
  text "ALTIUM DESIGNER VERSION:" at 12848.5,-923.5 h45
  text "an implementation. TI and/or its licensors do not warrant that the design is production worthy. You should" at 6329.01,-943.33 h45
  text "completely validate and test your design implementation to confirm the system functionality for your application." at 6374,-1056 h45
  text ".print_Scale" at 11393.5,-1056.83 h70
  text ".Application_BuildNumber" at 12899,-1056.83 h70
  text "1" at 739.84,-1263.5 h70
  text "2" at 3235.5,-1263.5 h70
  text "3" at 5724.84,-1263.5 h70
  text "4" at 8231.51,-1263.5 h70
  text "5" at 10730.5,-1263.5 h70
  text "6" at 13235.5,-1263.5 h70
M10 Fab Notes:
  drawing of 185 lines, arcs and shapes, not listed
  text "DESIGN INFORMATION" at 12381.02,5910 h60
  text "MIN. TRACK WIDTH:" at 11736.46,5730 h60
  text "8" at 12832.7,5730 h60
  text "MIL" at 12987.46,5730 h60
  text "8" at 12848,5612 h60
  text "MIN. CLEARANCE:" at 11736.46,5598 h60
  text "mm" at 12987.46,5598 h60
  text "MIN. VIA PAD SIZE:" at 11736.46,5466 h60
  text "MIL" at 12987.46,5466 h60
  text "20" at 12781.71,5462 h60
  text "0.05mm (2MIL)" at 12431.46,5324.29 h60
  text "MINIMUM ANNULAR RING" at 11407.23,5320 h60
  text "EXTERNAL" at 13139.46,5320 h60
  text "PER" at 11607.23,5202 h60
  text "IPC-D-275 CLASS 2 LEVEL C" at 11827.23,5202 h60
  text "MIL, HOLES" at 13315.46,5089.71 h60
  text "+/-" at 12923,5089 h60
  text "+/-" at 13777,5089 h60
  text "REGISTRATION TOLERANCES:" at 11407.23,5084 h60
  text "METAL" at 12607,5084 h60
  text "5" at 13183.2,5084 h60
  text "3" at 14016.2,5084 h60
  text "MIL" at 14132.46,5084 h60
  text "MATERIAL:" at 11332.46,4874.54 h60
  text "FR-4 High Tg" at 12318.9,4734.21 h60
  text "FR-4" at 13815,4734 h60
  text "X" at 13059,4730 h60
  text "FR-408" at 11753.46,4725.64 h60
  text "OTHER" at 13241.46,4725.64 h60
  text "62 MIL (1.6mm) +/-10%" at 12073.56,4562.92 h60
  text "THICKNESS:" at 11407.23,4558.64 h60
  text "X" at 11945.4,4558.64 h60
  text "OTHER" at 13358.46,4558.64 h60
  text "TOLERANCE:" at 11407.23,4400.64 h60
  text "X" at 12246.53,4400.64 h60
  text "ANSI IPC-6012 TYPE 3 CLASS 2" at 12433.48,4400.64 h60
  text "OTHER +/-" at 12433.46,4244.64 h60
  text "BOW & TWIST:" at 11407.23,4087.64 h60
  text "X" at 12246.53,4087.64 h60
  text "ANSI IPC-6012 TYPE 3 CLASS 2" at 12433.48,4087.64 h60
  text "OTHER +/-" at 12433.46,3929.13 h60
  text "DRILLING:" at 11332.46,3790.64 h60
  text "REFERENCE:" at 11407.23,3673.64 h60
  text "X" at 12055.46,3673.64 h60
  text "AS SHOWN" at 12242.46,3673.64 h60
  text "X" at 12956.46,3673.64 h60
  text "NC_DRILL FILES" at 13093.46,3673.64 h60
  text "PTH MIN COPPER THICKNESS:" at 11407.23,3515.64 h60
  text "X" at 12757.46,3515.64 h60
  text "1MIL" at 12894.46,3515.64 h60
  text "OTHER" at 13391.46,3515.64 h60
  text "BOARD FINISH:" at 11332.46,3356.64 h60
  text "SILKSCREEN:" at 11487.68,3238.64 h60
  text "X" at 12436.46,3238.64 h60
  text "TOP" at 12562.46,3238.64 h60
  text "X" at 12946.46,3238.64 h60
  text "BOTTOM" at 13073.46,3238.64 h60
  text "SILKSCREEN COLOR:" at 11487.68,3071.64 h60
  text "WHITE" at 12562.46,3071.64 h60
  text "OTHER" at 13073.46,3071.64 h60
  text "X" at 12446,3065 h60
  text "SOLDER RESIST COLOR:" at 11487.68,2901.64 h60
  text "X" at 12055.42,2742.44 h60
  text "GREEN" at 12182.46,2742.44 h60
  text "BLUE" at 12773.46,2742.44 h60
  text "OTHER" at 13311.46,2742.44 h60
  text "IMMERSION GOLD (ENIG)" at 12393.46,2553.92 h60
  text "ENEPIG" at 13731,2550.64 h60
  text "SURFACE FINISH:" at 11332.46,2549.64 h60
  text "HASL" at 13693,2407 h60
  text "X" at 12913,2394 h60
  text "IMM. TIN/SILVER OR EQUIV" at 11662,2392.64 h60
  text "OTHER" at 13093.46,2392.64 h60
  text "ARRAY/PANEL:" at 11332.46,2213.64 h60
  text "X" at 12206,2214 h60
  text "CUT AND TRIM PER MECH LAYER 1" at 12393.46,2209.35 h60
  text "N.C. ROUTE" at 12393.46,2057.64 h60
  text "V. SCORE" at 13259.46,2057.64 h60
  text "CERTIFICATION:" at 11332.46,1920.64 h60
  text "MATERIALS AND WORKMANSHIP FOR ALL PCBS" at 12057.46,1920.64 h60
  text "TO MEET OR EXCEED THE REQUIREMENTS OF:" at 12057.46,1822.64 h60
  text "X" at 11683.96,1686.13 h60
  text "ANSI IPC-A-600F CLASS ->" at 11822.96,1686.13 h60
  text "X" at 13462.02,1686.13 h60
  text "2" at 13580.96,1686.14 h60
  text "1" at 13265.96,1684.64 h60
  text "3" at 13934.96,1684.64 h60
  text "X" at 11686.02,1526.64 h60
  text "UL 94V-0" at 11822.96,1526.64 h60
  text "X" at 12498.02,1526.64 h60
  text "RoHS" at 12634.96,1526.64 h60
  text "OTHER" at 13279.36,1526.64 h60
  text "PER ORDER" at 13676.42,1526.64 h60
  text "ADDITIONAL REQUIREMENTS:" at 11332.46,1385.64 h60
  text "MICROSECTION:" at 11407.23,1270.64 h60
  text "YES" at 12312.96,1270.64 h60
  text "REQUIRED" at 13174.46,1114.49 h60
  text "BARE BOARD ELEC. TEST:" at 11407.23,1111.64 h60
  text "NONE" at 12712.96,1111.64 h60
  text "PER ORDER" at 13766.46,1111.64 h60
  text "X" at 13648,1107 h60
  text "MANUFACTURER'S UL:" at 11407.23,954.64 h60
  text "RAIL" at 12572.96,950.35 h60
  text "METAL" at 13064.77,950.35 h60
  text "X" at 13440,950 h60
  text "SILK" at 13576.46,950.35 h60
  text ".Layer_Name" at 577,-858.49 h60
M11 Gerber Information:
  lines w10: -292,-930.17 6308,-930.17 ; -292,-726.83 6310,-726.83 ; -292,-523.5 -292,-1133.5 3713,-1133.5 6310,-1133.5 6310,-523.5 -291.5,-523.5 -291.5,-1133.5 1284,-1133.5 ; 2173,-1133.5 2173,-523.5 ; 3440,-726.83 3440,-523.5 ; 4280,-726.83 4280,-523.5 ; 4902,-1140 4902,-937.17
  text "ALL ARTWORK VIEWED FROM TOP SIDE" at -228.5,-655.67 h60
  text "BOARD #:" at 2248,-655.67 h60
  text ".PRJ_Number" at 2793.5,-655.67 h60
  text "REV:" at 3638,-655.67 h60
  text ".PCB_Rev" at 3929.5,-655.67 h60
  text "SVN REV:" at 4476,-655.67 h60
  text ".VersionControl_RevNumber" at 4982,-655.67 h60
  text "LAYER NAME =" at -228.5,-858.49 h60
  text "PLOT NAME =" at -228.5,-1064.34 h60
  text ".plot_File_Name" at 577,-1064.34 h60
  text "GENERATED    :" at 2250,-1064.34 h60
  text ".Print_Date" at 3119.5,-1064.34 h60
  text ".Print_Time" at 3848.5,-1064.34 h60
  text "TEXAS INSTRUMENTS" at 5113,-1064.34 h60
M12 Stackup:
  text ".Layer_Name" at 577,-858.49 h60
M13 Component Bodies Top:
  text ".Layer_Name" at 577,-858.49 h60
M14 Component Bodies Bottom:
  text ".Layer_Name" at 577,-858.49 h60
M15 Courtyards Top:
  text ".Layer_Name" at 577,-858.49 h60
M16 Courtyards Bottom:
  text ".Layer_Name" at 577,-858.49 h60
Drill Drawing:
  text ".Layer_Name" at 577,-858.49 h60

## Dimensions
0,0 to 0,2500 on M2 Board Dimensions
0,0 to 3000,0 on M2 Board Dimensions
0,-410.5 to 1000,-410.5 on M2 Board Dimensions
